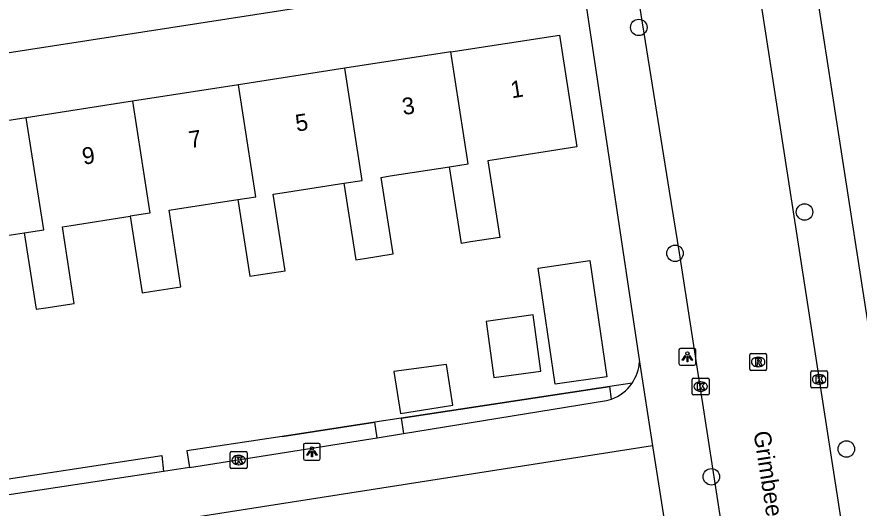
# Model space of a CAD drawing. Extents: x 160077 to 160945, y 386481 to 387498.
# Drawn here: x 160314.45 to 160364.4, y 387324.28 to 387353.43 of the extents above; entities that cross this region are included whole.
import ezdxf

# ---------------------------------------------------------------- set-up
doc = ezdxf.new("R2010")
doc.units = 0
for name, color, linetype in [('IMGEO_Boom', 7, 'Continuous'), ('IMGEO_Groenvoorziening', 7, 'Continuous'), ('IMGEO_Haag', 7, 'Continuous'), ('IMGEO_Hek', 7, 'Continuous'), ('IMGEO_Kolk', 7, 'Continuous'), ('IMGEO_Lichtpunt', 7, 'Continuous'), ('IMGEO_Openbare_ruimte_label', 7, 'Continuous'), ('IMGEO_Pand', 7, 'Continuous'), ('IMGEO_Pand_nummerreeks', 7, 'Continuous'), ('IMGEO_Rijbaan_lokaal_open', 7, 'Continuous'), ('IMGEO_Rioolput', 7, 'Continuous'), ('IMGEO_Voetpad_open', 7, 'Continuous')]:
    doc.layers.add(name, color=color, linetype=linetype)

msp = doc.modelspace()

# ---------------------------------------------------------------- linework, layer by layer
at = {"layer": 'IMGEO_Boom'}
for centre in [(160351.331, 387352.8), (160361.162, 387341.848), (160353.483, 387339.399), (160363.643, 387327.786), (160355.634, 387326.139)]:
    msp.add_circle(centre, 0.489, dxfattribs=at)
at = {"layer": 'IMGEO_Groenvoorziening'}
msp.add_lwpolyline([(160350.932, 387331.689), (160349.608, 387331.488)], dxfattribs=at)
at = {"layer": 'IMGEO_Haag'}
for points in [[(160349.608, 387331.488), (160337.241, 387329.611)], [(160349.705, 387330.742), (160349.608, 387331.488)], [(160335.674, 387329.373), (160330.176, 387328.538), (160324.528, 387327.681), (160324.679, 387326.687)], [(160311.864, 387325.704), (160323.038, 387327.4), (160323.143, 387326.454)]]:
    msp.add_lwpolyline(points, dxfattribs=at)
at = {"layer": 'IMGEO_Hek'}
for points in [[(160337.241, 387329.611), (160349.608, 387331.488)], [(160330.176, 387328.538), (160335.674, 387329.373)], [(160311.864, 387325.704), (160323.038, 387327.4)]]:
    msp.add_lwpolyline(points, dxfattribs=at)
at = {"layer": 'IMGEO_Kolk'}
for p, q in [((160361.527, 387331.493), (160361.527, 387332.345)), ((160361.602, 387332.419), (160362.454, 387332.419)), ((160362.015, 387332.199), (160362.04, 387332.199)), ((160362.528, 387332.345), (160362.528, 387331.493)), ((160354.502, 387331.066), (160354.502, 387331.918)), ((160354.577, 387331.992), (160355.429, 387331.992)), ((160354.99, 387331.772), (160355.015, 387331.772)), ((160355.503, 387331.918), (160355.503, 387331.066)), ((160362.038, 387331.639), (160362.013, 387331.639)), ((160355.013, 387331.212), (160354.988, 387331.212)), ((160362.454, 387331.419), (160361.602, 387331.419)), ((160355.429, 387330.992), (160354.577, 387330.992)), ((160327.101, 387326.703), (160327.101, 387327.555)), ((160327.176, 387327.629), (160328.028, 387327.629)), ((160328.102, 387327.555), (160328.102, 387326.703)), ((160327.589, 387327.409), (160327.614, 387327.409)), ((160328.028, 387326.629), (160327.176, 387326.629)), ((160327.612, 387326.849), (160327.587, 387326.849))]:
    msp.add_line(p, q, dxfattribs=at)
for points in [[(160361.527, 387331.493), (160361.527, 387332.345)], [(160361.602, 387332.419), (160362.454, 387332.419)], [(160361.848, 387332.119), (160361.971, 387332.119), (160361.971, 387331.968), (160362.101, 387332.119), (160362.265, 387332.119), (160362.119, 387331.968), (160362.272, 387331.719), (160362.12, 387331.719), (160362.035, 387331.883), (160361.971, 387331.816), (160361.971, 387331.719), (160361.848, 387331.719), (160361.848, 387332.119)], [(160362.528, 387332.345), (160362.528, 387331.493)], [(160354.502, 387331.066), (160354.502, 387331.918)], [(160354.577, 387331.992), (160355.429, 387331.992)], [(160354.823, 387331.692), (160354.946, 387331.692), (160354.946, 387331.541), (160355.076, 387331.692), (160355.24, 387331.692), (160355.094, 387331.541), (160355.247, 387331.292), (160355.095, 387331.292), (160355.01, 387331.456), (160354.946, 387331.389), (160354.946, 387331.292), (160354.823, 387331.292), (160354.823, 387331.692)], [(160355.503, 387331.918), (160355.503, 387331.066)], [(160362.454, 387331.419), (160361.602, 387331.419)], [(160355.429, 387330.992), (160354.577, 387330.992)], [(160327.101, 387326.703), (160327.101, 387327.555)], [(160327.176, 387327.629), (160328.028, 387327.629)], [(160328.102, 387327.555), (160328.102, 387326.703)], [(160327.422, 387327.329), (160327.545, 387327.329), (160327.545, 387327.178), (160327.675, 387327.329), (160327.839, 387327.329), (160327.693, 387327.178), (160327.846, 387326.929), (160327.694, 387326.929), (160327.609, 387327.093), (160327.545, 387327.026), (160327.545, 387326.929), (160327.422, 387326.929), (160327.422, 387327.329)], [(160328.028, 387326.629), (160327.176, 387326.629)]]:
    msp.add_lwpolyline(points, dxfattribs=at)
for centre, start, end in [((160361.604, 387332.343), 91.552, 178.448), ((160361.604, 387332.343), 91.552, 178.448), ((160362.452, 387332.343), 1.552, 88.448), ((160362.452, 387332.343), 1.552, 88.448), ((160354.579, 387331.916), 91.552, 178.448), ((160354.579, 387331.916), 91.552, 178.448), ((160355.427, 387331.916), 1.552, 88.448), ((160355.427, 387331.916), 1.552, 88.448), ((160354.579, 387331.068), 181.552, 268.448), ((160354.579, 387331.068), 181.552, 268.448), ((160355.427, 387331.068), 271.552, 358.448), ((160355.427, 387331.068), 271.552, 358.448), ((160361.604, 387331.495), 181.552, 268.448), ((160361.604, 387331.495), 181.552, 268.448), ((160362.452, 387331.495), 271.552, 358.448), ((160362.452, 387331.495), 271.552, 358.448), ((160327.178, 387327.553), 91.552, 178.448), ((160327.178, 387327.553), 91.552, 178.448), ((160328.026, 387327.553), 1.552, 88.448), ((160328.026, 387327.553), 1.552, 88.448), ((160327.178, 387326.705), 181.552, 268.448), ((160327.178, 387326.705), 181.552, 268.448), ((160328.026, 387326.705), 271.552, 358.448), ((160328.026, 387326.705), 271.552, 358.448)]:
    msp.add_arc(centre, 0.0765, start, end, dxfattribs=at)
for centre, major_axis, ratio, start_param, end_param in [((160362.014, 387331.919), (-0.387, 0.002), 0.722429, 4.712389, 7.853982), ((160362.039, 387331.919), (-0.39, 0.002), 0.717154, 1.570796, 4.712389), ((160354.989, 387331.492), (-0.387, 0.002), 0.722429, 4.712389, 7.853982), ((160355.014, 387331.492), (-0.39, 0.002), 0.717154, 1.570796, 4.712389), ((160327.588, 387327.129), (-0.387, 0.002), 0.722429, 4.712389, 7.853982), ((160327.613, 387327.129), (-0.39, 0.002), 0.717154, 1.570796, 4.712389)]:
    msp.add_ellipse(centre, major_axis=major_axis, ratio=ratio, start_param=start_param, end_param=end_param, dxfattribs=at)
at = {"layer": 'IMGEO_Lichtpunt'}
for p, q in [((160353.715, 387333.663), (160353.715, 387332.856)), ((160353.715, 387333.663), (160353.715, 387332.856)), ((160354.617, 387333.758), (160353.809, 387333.758)), ((160354.617, 387333.758), (160353.809, 387333.758)), ((160354.711, 387332.856), (160354.711, 387333.663)), ((160354.711, 387332.856), (160354.711, 387333.663)), ((160353.809, 387332.762), (160354.617, 387332.762)), ((160353.809, 387332.762), (160354.617, 387332.762)), ((160332.352, 387328.122), (160331.544, 387328.122)), ((160332.352, 387328.122), (160331.544, 387328.122)), ((160331.45, 387328.027), (160331.45, 387327.22)), ((160331.45, 387328.027), (160331.45, 387327.22)), ((160332.446, 387327.22), (160332.446, 387328.027)), ((160332.446, 387327.22), (160332.446, 387328.027)), ((160331.544, 387327.126), (160332.352, 387327.126)), ((160331.544, 387327.126), (160332.352, 387327.126))]:
    msp.add_line(p, q, dxfattribs=at)
for points in [[(160354.089, 387333.327), (160354.128, 387333.299), (160353.94, 387333.037), (160353.902, 387333.064), (160354.089, 387333.327)], [(160354.191, 387333.279), (160354.238, 387333.279), (160354.238, 387332.957), (160354.191, 387332.957), (160354.191, 387333.279)], [(160354.301, 387333.299), (160354.339, 387333.326), (160354.526, 387333.064), (160354.487, 387333.036), (160354.301, 387333.299)], [(160331.824, 387327.691), (160331.863, 387327.663), (160331.675, 387327.401), (160331.637, 387327.428), (160331.824, 387327.691)], [(160331.926, 387327.643), (160331.973, 387327.643), (160331.973, 387327.321), (160331.926, 387327.321), (160331.926, 387327.643)], [(160332.036, 387327.663), (160332.074, 387327.69), (160332.261, 387327.428), (160332.222, 387327.4), (160332.036, 387327.663)]]:
    msp.add_lwpolyline(points, dxfattribs=at)
for centre in [(160354.214, 387333.461), (160331.949, 387327.825)]:
    msp.add_circle(centre, 0.0994, dxfattribs=at)
for centre, start, end in [((160353.809, 387333.663), 90, 180), ((160353.809, 387333.663), 90, 180), ((160354.617, 387333.663), 0, 90), ((160354.617, 387333.663), 0, 90), ((160353.809, 387332.856), 180, 270), ((160353.809, 387332.856), 180, 270), ((160354.617, 387332.856), 270, 0), ((160354.617, 387332.856), 270, 360), ((160331.544, 387328.027), 90, 180), ((160331.544, 387328.027), 90, 180), ((160332.352, 387328.027), 0, 90), ((160332.352, 387328.027), 0, 90), ((160331.544, 387327.22), 180, 270), ((160331.544, 387327.22), 180, 270), ((160332.352, 387327.22), 270, 0), ((160332.352, 387327.22), 270, 360)]:
    msp.add_arc(centre, 0.0946, start, end, dxfattribs=at)
at = {"layer": 'IMGEO_Pand'}
for points in [[(160340.188, 387351.351), (160346.623, 387352.35), (160347.655, 387345.706), (160342.898, 387344.967), (160342.377, 387344.886), (160343.083, 387340.342), (160341.343, 387340.072), (160340.809, 387339.989), (160340.103, 387344.533)], [(160340.188, 387351.351), (160333.893, 387350.373)], [(160340.103, 387344.533), (160341.22, 387344.705), (160340.188, 387351.351)], [(160333.893, 387350.373), (160327.599, 387349.396)], [(160333.839, 387343.561), (160334.925, 387343.727), (160333.893, 387350.373)], [(160327.599, 387349.396), (160321.304, 387348.418)], [(160327.551, 387342.584), (160328.631, 387342.75), (160327.599, 387349.396)], [(160321.304, 387348.418), (160315.01, 387347.441)], [(160321.304, 387348.418), (160322.336, 387341.772), (160321.177, 387341.594)], [(160315.01, 387347.441), (160308.715, 387346.464)], [(160314.892, 387340.618), (160316.042, 387340.795), (160315.01, 387347.441)], [(160333.839, 387343.561), (160334.545, 387339.017), (160335.068, 387339.098), (160336.759, 387339.36), (160336.053, 387343.904), (160336.593, 387343.988), (160340.103, 387344.533)], [(160327.551, 387342.584), (160328.257, 387338.04), (160328.784, 387338.122), (160330.362, 387338.367), (160329.656, 387342.911), (160330.178, 387342.992), (160333.839, 387343.561)], [(160321.177, 387341.594), (160321.883, 387337.051), (160322.374, 387337.127), (160324.179, 387337.408), (160323.473, 387341.951), (160323.984, 387342.03), (160327.551, 387342.584)], [(160314.892, 387340.618), (160315.598, 387336.075), (160316.173, 387336.164), (160317.854, 387336.425), (160317.148, 387340.969), (160317.677, 387341.051), (160321.177, 387341.594)], [(160308.596, 387339.638), (160309.301, 387335.096), (160309.752, 387335.166), (160311.477, 387335.434), (160310.771, 387339.978), (160311.274, 387340.056), (160314.892, 387340.618)], [(160345.364, 387338.52), (160348.438, 387338.968), (160349.442, 387332.078), (160346.368, 387331.63), (160345.364, 387338.52)], [(160342.29, 387335.359), (160342.745, 387332.025), (160345.523, 387332.405), (160345.068, 387335.739), (160342.29, 387335.359)], [(160336.799, 387332.389), (160337.197, 387329.891), (160340.314, 387330.388), (160339.929, 387332.8), (160336.799, 387332.389)]]:
    msp.add_lwpolyline(points, dxfattribs=at)
at = {"layer": 'IMGEO_Rijbaan_lokaal_open'}
for points in [[(160352.799, 387391.033), (160358.665, 387353.61), (160366.562, 387302.662), (160369.173, 387285.284)], [(160357.73, 387313.614), (160353.738, 387339.43), (160353.156, 387343.079), (160351.403, 387354.063), (160351.293, 387354.598)]]:
    msp.add_lwpolyline(points, dxfattribs=at)
at = {"layer": 'IMGEO_Rioolput'}
for p, q in [((160357.911, 387332.525), (160357.911, 387333.377)), ((160357.986, 387333.451), (160358.838, 387333.451)), ((160358.399, 387333.231), (160358.424, 387333.231)), ((160358.912, 387333.377), (160358.912, 387332.525)), ((160358.422, 387332.671), (160358.397, 387332.671)), ((160358.838, 387332.451), (160357.986, 387332.451))]:
    msp.add_line(p, q, dxfattribs=at)
for points in [[(160357.911, 387332.525), (160357.911, 387333.377)], [(160357.986, 387333.451), (160358.838, 387333.451)], [(160358.5, 387333.149), (160358.248, 387333.151), (160358.248, 387332.751)], [(160358.426, 387333.07), (160358.372, 387333.07), (160358.372, 387332.989)], [(160358.912, 387333.377), (160358.912, 387332.525)], [(160358.248, 387332.751), (160358.372, 387332.751), (160358.372, 387332.913), (160358.383, 387332.913)], [(160358.372, 387332.989), (160358.424, 387332.989)], [(160358.43, 387332.884), (160358.501, 387332.751), (160358.641, 387332.751), (160358.576, 387332.877)], [(160358.838, 387332.451), (160357.986, 387332.451)]]:
    msp.add_lwpolyline(points, dxfattribs=at)
for centre, radius, start, end in [((160357.988, 387333.375), 0.0765, 91.552, 178.448), ((160357.988, 387333.375), 0.0765, 91.552, 178.448), ((160358.432, 387332.974), 0.0964, 77.0061, 93.1865), ((160358.446, 387333.031), 0.0378, 276.6634, 79.6772), ((160358.499, 387333.039), 0.109, 350.3612, 89.416), ((160358.836, 387333.375), 0.0765, 1.552, 88.448), ((160358.836, 387333.375), 0.0765, 1.552, 88.448), ((160358.382, 387332.86), 0.0533, 26.0293, 88.6989), ((160358.408, 387333.178), 0.19, 274.7715, 282.9687), ((160358.497, 387333.039), 0.112, 277.5842, 350.9817), ((160358.481, 387332.824), 0.108, 29.5134, 73.7905), ((160357.988, 387332.527), 0.0765, 181.552, 268.448), ((160357.988, 387332.527), 0.0765, 181.552, 268.448), ((160358.836, 387332.527), 0.0765, 271.552, 358.448), ((160358.836, 387332.527), 0.0765, 271.552, 358.448)]:
    msp.add_arc(centre, radius, start, end, dxfattribs=at)
for centre, major_axis, ratio, start_param, end_param in [((160358.398, 387332.951), (-0.387, 0.002), 0.722429, 4.712389, 7.853982), ((160358.423, 387332.951), (-0.39, 0.002), 0.717154, 1.570796, 4.712389)]:
    msp.add_ellipse(centre, major_axis=major_axis, ratio=ratio, start_param=start_param, end_param=end_param, dxfattribs=at)
at = {"layer": 'IMGEO_Voetpad_open'}
for points in [[(160372.658, 387285.339), (160359.174, 387372.354)], [(160277.066, 387345.597), (160345.165, 387356.158)], [(160348.215, 387354.083), (160351.371, 387332.958)], [(160351.371, 387332.958), (160352.153, 387327.971)], [(160337.378, 387328.71), (160349.424, 387330.658), (160349.566, 387330.696), (160349.705, 387330.742)], [(160337.241, 387329.611), (160335.674, 387329.373)], [(160337.241, 387329.611), (160337.378, 387328.71)], [(160335.813, 387328.457), (160335.674, 387329.373)], [(160335.813, 387328.457), (160337.378, 387328.71)], [(160324.679, 387326.687), (160335.813, 387328.457)], [(160352.153, 387327.971), (160310.416, 387321.441), (160314.017, 387298.456), (160314.061, 387298.234), (160314.124, 387298.017), (160314.206, 387297.806), (160314.307, 387297.603), (160314.426, 387297.41), (160314.561, 387297.229), (160314.712, 387297.06), (160314.749, 387297.023)], [(160352.153, 387327.971), (160355.398, 387307.291), (160355.751, 387304.187)], [(160324.679, 387326.687), (160323.143, 387326.454)], [(160323.143, 387326.454), (160312.006, 387324.767)]]:
    msp.add_lwpolyline(points, dxfattribs=at)
for centre, radius, start, end in [((160348.839, 387333.123), 2.537, 325.5727, 356.262), ((160348.846, 387333.123), 2.531, 289.8345, 325.4875)]:
    msp.add_arc(centre, radius, start, end, dxfattribs=at)

# ---------------------------------------------------------------- texts
at = {"layer": 'IMGEO_Openbare_ruimte_label'}
msp.add_text('Grimbeertlaan', height=1, rotation=278.8028, dxfattribs=at).set_placement((160358.131, 387328.783))
at = {"layer": 'IMGEO_Pand_nummerreeks'}
for s, p in [('1', (160343.805, 387348.593)), ('3', (160337.37, 387347.595)), ('5', (160331.047, 387346.613)), ('7', (160324.725, 387345.631)), ('9', (160318.402, 387344.649))]:
    msp.add_text(s, height=1, rotation=8.8293, dxfattribs=at).set_placement(p)

doc.saveas('drawing.dxf')
